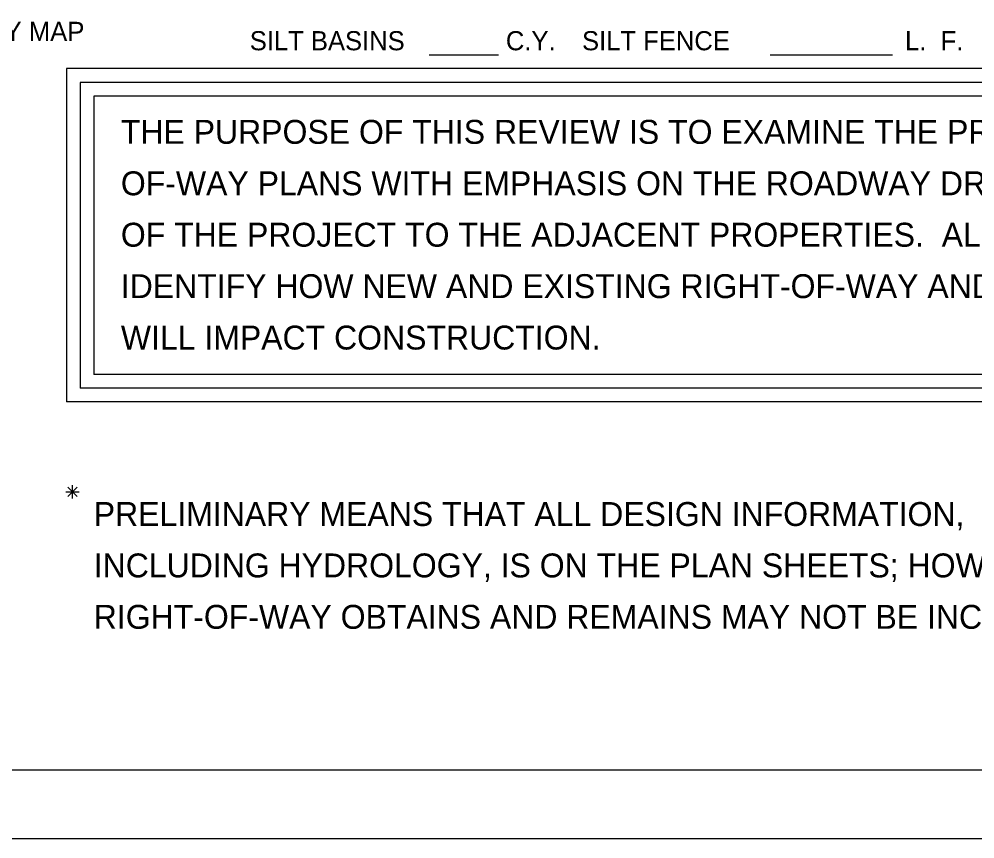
# Model space of a CAD drawing. Extents: x -796 to 2793, y -4650 to 4425.
# Drawn here: x 2221.5 to 2569.2, y 3300 to 3598.1 of the extents above; entities that cross this region are included whole.
import ezdxf

# ---------------------------------------------------------------- set-up
doc = ezdxf.new("R2010")
doc.units = 0
for name, color, linetype in [('RD_HC_CL', 7, 'Continuous'), ('RD_HC_Data', 7, 'Continuous'), ('RD_HC_Data_Tic', 7, 'Continuous'), ('RD_SHT_Bndy', 7, 'Continuous')]:
    doc.layers.add(name, color=color, linetype=linetype)

msp = doc.modelspace()

# ---------------------------------------------------------------- linework, layer by layer
at = {"layer": 'RD_HC_CL'}
msp.add_lwpolyline([(986.45, 4400), (2782.44, 4400), (2782.44, 3300), (986.45, 3300)], close=True, dxfattribs=at)
at = {"layer": 'RD_HC_Data'}
for p, q in [((2370.7, 3585.19), (2395.82, 3585.19)), ((2494.67, 3585.19), (2539.22, 3585.19)), ((2747.79, 3580.14), (2238.69, 3580.14)), ((2238.69, 3580.14), (2238.69, 3458.92)), ((2742.79, 3575.14), (2243.69, 3575.14)), ((2243.69, 3575.14), (2243.69, 3463.92)), ((2737.79, 3570.14), (2248.69, 3570.14)), ((2248.69, 3570.14), (2248.69, 3468.92)), ((2737.79, 3468.92), (2248.69, 3468.92)), ((2742.79, 3463.92), (2243.69, 3463.92)), ((2747.79, 3458.92), (2238.69, 3458.92)), ((2240.89, 3423.8), (2240.89, 3428.59)), ((2238.49, 3426.2), (2243.28, 3426.2)), ((2242.6, 3424.52), (2239.18, 3427.88)), ((2239.2, 3424.5), (2242.58, 3427.89)), ((2760, 3300), (1000, 3300))]:
    msp.add_line(p, q, dxfattribs=at)
msp.add_lwpolyline([(1082.45, 4375), (2757.45, 4375), (2757.45, 3325), (1082.45, 3325)], close=True, dxfattribs=at)

# ---------------------------------------------------------------- texts
at = {"layer": 'RD_HC_Data_Tic'}
for s, height, p in [('SILT BASINS', 6.9601, (2305.37, 3586.8)), ('C.Y.', 6.96, (2398.54, 3586.8)), ('SILT FENCE', 6.96, (2426.26, 3586.8)), ('L.  F.', 6.96, (2543.78, 3586.8)), ('THE PURPOSE OF THIS REVIEW IS TO EXAMINE THE PRELIMINARY RIGHT-', 8.7001, (2258.47, 3552.78)), ('OF-WAY PLANS WITH EMPHASIS ON THE ROADWAY DRAINAGE AND THE IMPACT', 8.7001, (2258.47, 3534.07)), ('OF THE PROJECT TO THE ADJACENT PROPERTIES.  ALSO THIS REVIEW WILL', 8.7001, (2258.47, 3515.37)), ('IDENTIFY HOW NEW AND EXISTING RIGHT-OF-WAY AND ROADWAY DESIGNS', 8.7001, (2258.47, 3496.67)), ('WILL IMPACT CONSTRUCTION.', 8.7001, (2258.47, 3477.97)), ('PRELIMINARY MEANS THAT ALL DESIGN INFORMATION,', 8.7001, (2248.62, 3413.8)), ('INCLUDING HYDROLOGY, IS ON THE PLAN SHEETS; HOWEVER,', 8.7001, (2248.62, 3395.1)), ('RIGHT-OF-WAY OBTAINS AND REMAINS MAY NOT BE INCLUDED.', 8.7001, (2248.62, 3376.4))]:
    msp.add_text(s, height=height, dxfattribs=at).set_placement(p)
at = {"layer": 'RD_SHT_Bndy'}
msp.add_text('YORK COUNTY MAP', height=7, dxfattribs=at).set_placement((2153.7, 3590.15))

doc.saveas('drawing.dxf')
